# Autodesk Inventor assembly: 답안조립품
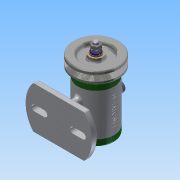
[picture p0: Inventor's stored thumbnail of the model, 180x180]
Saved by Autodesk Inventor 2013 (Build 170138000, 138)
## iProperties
Created: 2017-12
Part Number: 답안조립품
Document SubType Name: Assembly
Designer: Administrator
Author: Administrator
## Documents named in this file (14)
- C:\Users\Administrator\Desktop\471208V1020\답안조립품.iam
- C:\Users\Administrator\Desktop\471208V1020\V벨트풀리.ipt
- C:\Users\Administrator\Desktop\471208V1020\고무캡.ipt
- C:\Users\Administrator\Desktop\471208V1020\너트 M 8.ipt
- C:\Users\Administrator\Desktop\471208V1020\뒤커버.ipt
- C:\Users\Administrator\Desktop\471208V1020\베어링 15 x 32 x 9.ipt
- C:\Users\Administrator\Desktop\471208V1020\본체.ipt
- C:\Users\Administrator\Desktop\471208V1020\볼트 M4 x 12.ipt
- C:\Users\Administrator\Desktop\471208V1020\스프링와셔 8.ipt
- C:\Users\Administrator\Desktop\471208V1020\앞커버.ipt
- C:\Users\Administrator\Desktop\471208V1020\오일 실 15 25 7.ipt
- C:\Users\Administrator\Desktop\471208V1020\와셔 8x17.ipt
- C:\Users\Administrator\Desktop\471208V1020\축.ipt
- C:\Users\Administrator\Desktop\471208V1020\키 3 x 3 x 12.ipt
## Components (2 placed, 2 different names)
1. V벨트풀리:1
2. 고무캡:1 — 각도:1
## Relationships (1: Angle 1)
- 각도:1 [Angle]: 고무캡:1
